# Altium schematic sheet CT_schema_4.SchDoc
size 255 x 245 mm
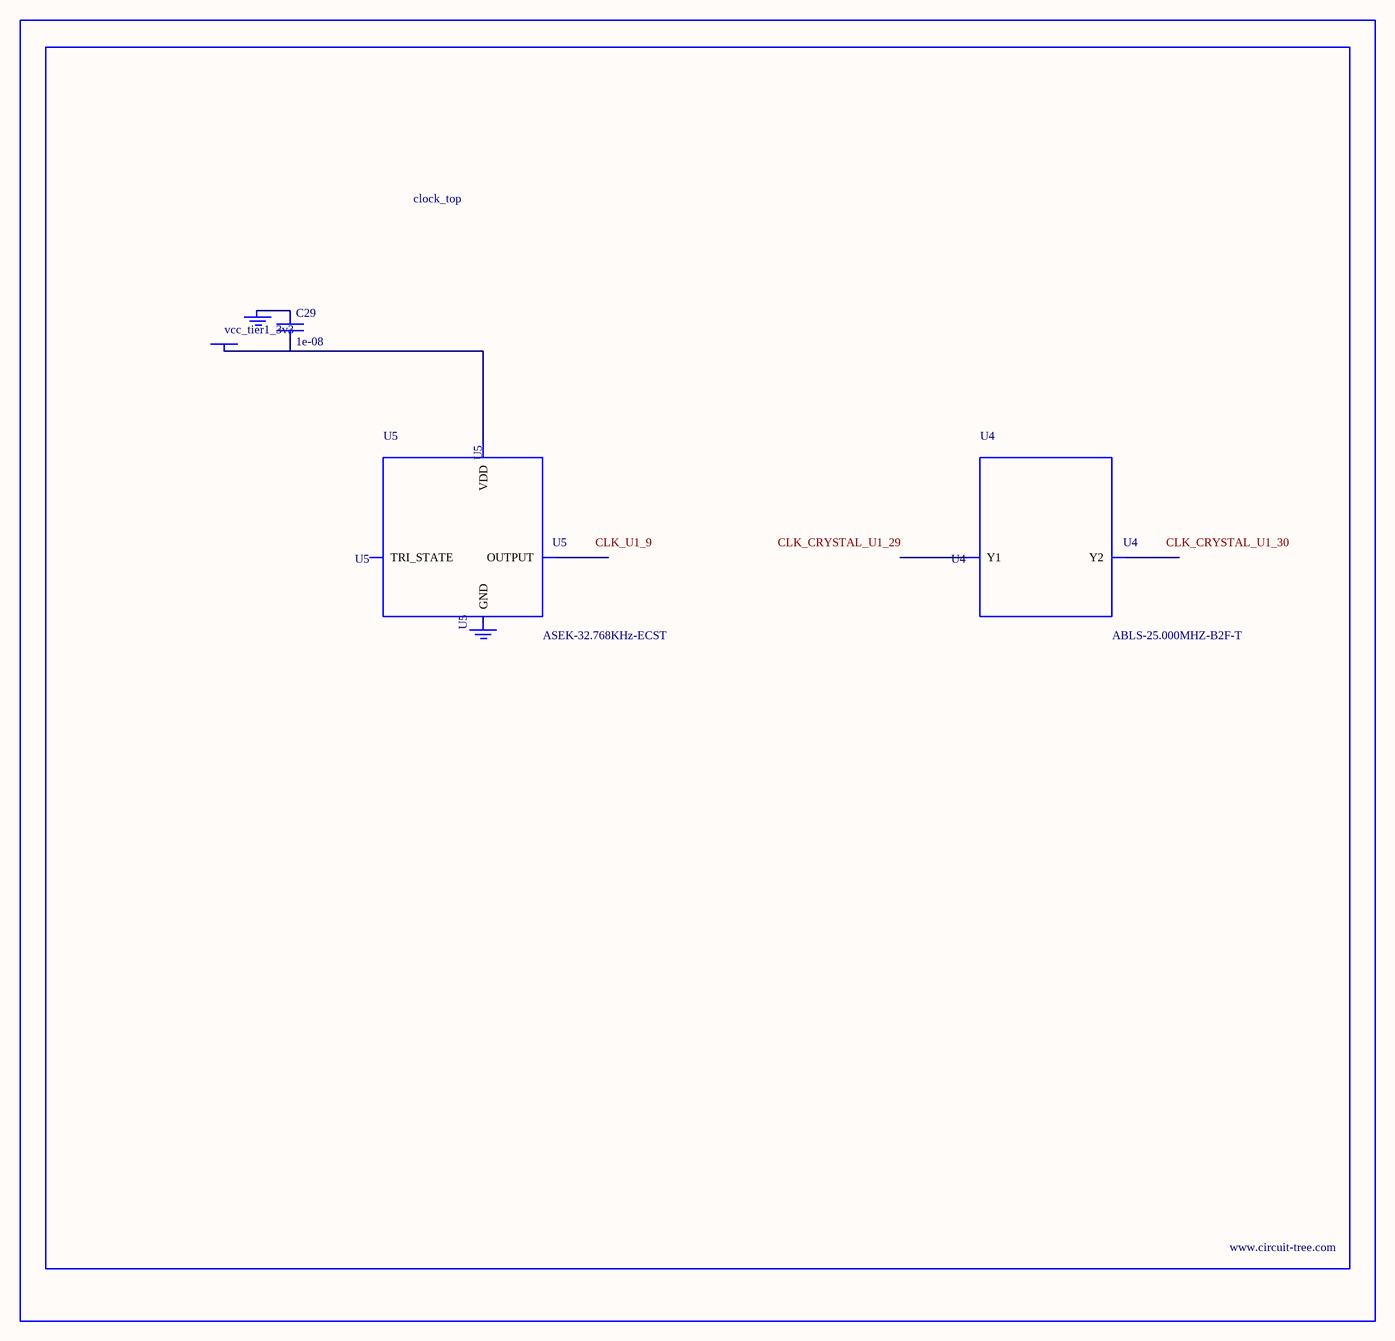
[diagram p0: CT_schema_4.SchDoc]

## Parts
BORDER3  (no value)
C29  1e-08  [C0402]
GND_INSTANCE_3_0  (no value)
GND_INSTANCE_3_1  (no value)
POWER_INSTANCE_3_0  vcc_tier1_3v3
U4  ABLS-25.000MHZ-B2F-T  [ABLS-25.000MHZ-B2F-T]
U5  ASEK-32.768KHz-ECST  [ASEK]

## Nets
NetC29_1: C29.1 GND_INSTANCE_3_0.0(GND)
NetC29_2: C29.2 POWER_INSTANCE_3_0.0(PWR) U5.4(VDD)

Not connected (* = marked no-connect by the designer): GND_INSTANCE_3_1 0(GND); U4 1(Y1) 2(Y2); U5 1(TRI_STATE) 2(GND) 3(OUTPUT)

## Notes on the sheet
- Labels drawn without touching a wire or pin: CLK_CRYSTAL_U1_29, CLK_CRYSTAL_U1_30, CLK_U1_9

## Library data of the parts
BORDER3 = BORDER_PAGE3
C29 = C0402C103K3RAC
GND_INSTANCE_3_0 GND_INSTANCE_3_1 = GND
POWER_INSTANCE_3_0 = PWR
